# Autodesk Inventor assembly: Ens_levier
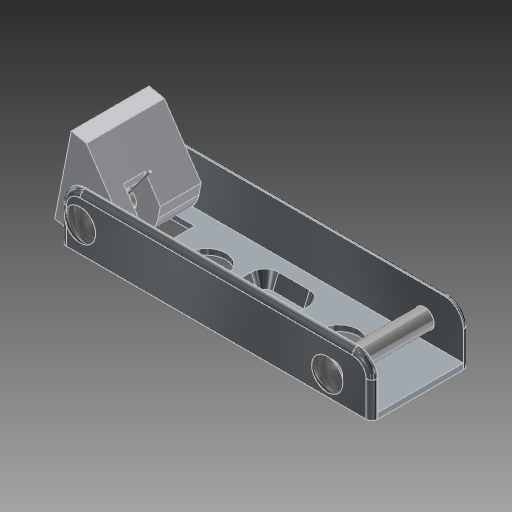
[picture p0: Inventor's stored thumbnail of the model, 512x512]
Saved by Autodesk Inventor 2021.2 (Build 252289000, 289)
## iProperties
Created: 2018-06
Part Number: Ens_levier
Material: Générique
Document SubType Name: Assembly
Designer: Fabian Perrée
Mass: 50.2616 g
Surface Area: 113.894 cm^2
Volume: 10.4343 cm^3
Density: 4.81695 g/cm^3
Author: Fabian Perrée
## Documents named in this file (6)
- C:\Users\Fabian\Google Drive\04_CAO-DAO\01_Exercices\01_Inventor\01_Fichiers_exercice_Inventor\01_Definitif\Capteur\Ens_levier\Ens_levier.iam
- C:\Users\Fabian\Google Drive\04_CAO-DAO\01_Exercices\01_Inventor\01_Fichiers_exercice_Inventor\01_Definitif\Capteur\Ens_levier\Composants\Levier.ipt
- C:\Users\Fabian\Google Drive\04_CAO-DAO\01_Exercices\01_Inventor\01_Fichiers_exercice_Inventor\01_Definitif\Capteur\Ens_levier\Composants\Butee.ipt
- C:\Users\Fabian\Google Drive\04_CAO-DAO\01_Exercices\01_Inventor\01_Fichiers_exercice_Inventor\01_Definitif\Capteur\Ens_levier\Composants\Axe_25.ipt
- C:\Users\Fabian\Google Drive\04_CAO-DAO\01_Exercices\01_Inventor\01_Fichiers_exercice_Inventor\01_Definitif\Capteur\Ens_levier\Composants\Axe_28.ipt
- C:\Users\Fabian\Google Drive\04_CAO-DAO\01_Exercices\01_Inventor\01_Fichiers_exercice_Inventor\01_Definitif\Capteur\Ens_levier\Design Accelerator\Ressort de torsion1.iam
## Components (5 placed, 5 different names)
1. Levier:1 — Placage:4, Logement:2
2. Butee:1 — Tangente:1, Tangente:2
3. Axe_25:1 — Placage:3
4. Axe_28:1 — Logement:2
5. Ressort de torsion:1 [sub-assembly] — Placage:3, Tangente:1, Tangente:2, Placage:4
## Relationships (5: Mate 2, Tangent 2, Insert 1)
- Placage:3 [Mate]: Axe_25:1 ↔ Ressort de torsion:1
- Tangente:1: Butee:1 ↔ Ressort de torsion:1
- Tangente:2: Butee:1 ↔ Ressort de torsion:1
- Placage:4 [Mate]: Levier:1 ↔ Ressort de torsion:1
- Logement:2 [Insert]: Levier:1 ↔ Axe_28:1
